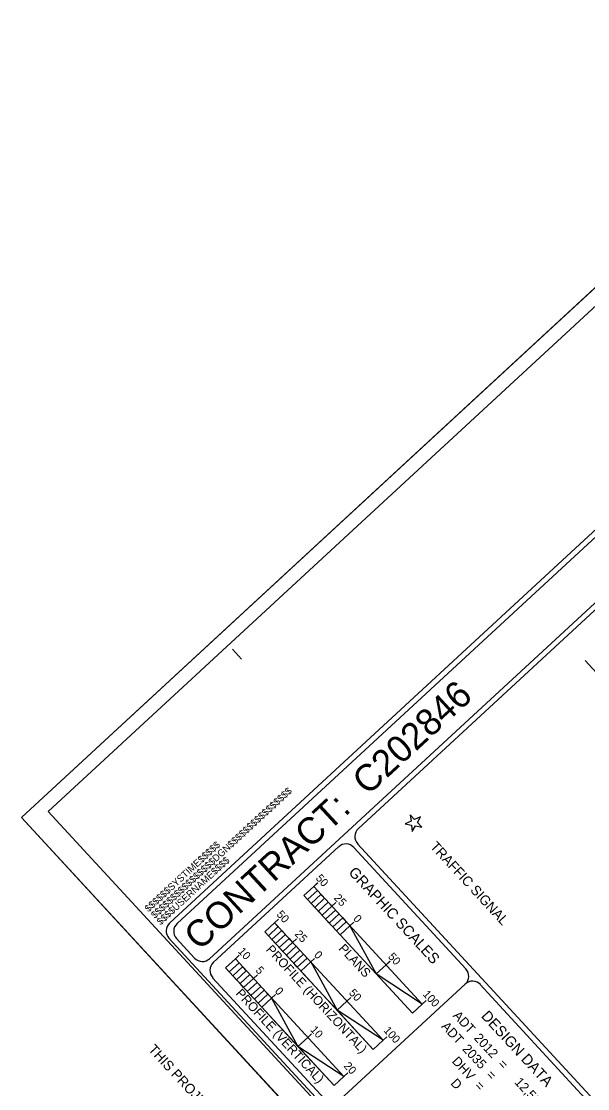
# Model space of a CAD drawing. Extents: x 1695041 to 1706254, y 786537 to 798223.
# Drawn here: x 1700402 to 1701995, y 795222 to 798223 of the extents above; entities that cross this region are included whole.
import ezdxf

# ---------------------------------------------------------------- set-up
doc = ezdxf.new("R2010")
doc.units = 0
for name, color, linetype in [('Old_Level_1', 7, 'Continuous'), ('Old_Level_23', 7, 'Continuous'), ('Prop RDY Traffic Signal CELL', 7, 'Continuous'), ('Sheet Cutting Line CELL', 7, 'Continuous'), ('Sheet Data Field CELL', 7, 'Continuous'), ('Sheet Plot Border Inside CELL', 7, 'Continuous'), ('Sheet Plot Border Outside CELL', 7, 'Continuous'), ('Sheet Title CELL', 7, 'Continuous')]:
    doc.layers.add(name, color=color, linetype=linetype)

msp = doc.modelspace()

# ---------------------------------------------------------------- linework, layer by layer
at = {"layer": 'Old_Level_1'}
msp.add_line((1702586.7, 795776.6), (1701987.7, 796425.6), dxfattribs=at)
at = {"layer": 'Prop RDY Traffic Signal CELL'}
msp.add_lwpolyline([(1701508.4, 795978.9), (1701496.1, 795992.3), (1701498.3, 795974.3), (1701481.8, 795966.7), (1701499.6, 795963.1), (1701501.7, 795945.1), (1701510.6, 795960.9), (1701528.4, 795957.4), (1701516.1, 795970.7), (1701524.9, 795986.5), (1701508.4, 795978.9)], dxfattribs=at)
at = {"layer": 'Sheet Cutting Line CELL'}
for p, q in [((1702826.9, 798222.8), (1700402.1, 795984.5)), ((1700402.1, 795984.5), (1703828.7, 792272.3))]:
    msp.add_line(p, q, dxfattribs=at)
at = {"layer": 'Sheet Data Field CELL'}
for p, q in [((1701224.7, 795790.5), (1701235.7, 795800.6)), ((1701275.5, 795735.3), (1701286.6, 795745.5)), ((1700797, 795667.2), (1700797, 795667.2)), ((1701428.2, 795570), (1701439.2, 795580.2)), ((1701529.9, 795459.8), (1701540.9, 795470))]:
    msp.add_line(p, q, dxfattribs=at)
at = {"layer": 'Sheet Plot Border Inside CELL'}
msp.add_lwpolyline([(1700478, 796001.5), (1703869.1, 792327.8), (1706194.9, 794474.8), (1702803.9, 798148.4)], close=True, dxfattribs=at)
at = {"layer": 'Sheet Plot Border Outside CELL'}
msp.add_lwpolyline([(1706253.6, 794510.5), (1702826.9, 798222.8), (1700402.1, 795984.5), (1703828.7, 792272.3)], close=True, dxfattribs=at)
at = {"layer": 'Sheet Title CELL'}
for p, q in [((1700931.8, 795587.5), (1703180.3, 797663.1)), ((1701349.8, 795953), (1703190.5, 797652)), ((1700996.3, 796457.5), (1701021.8, 796430)), ((1700996.3, 796457.5), (1701021.8, 796430)), ((1700942, 795576.5), (1701294.7, 795902.1)), ((1701337.1, 795900.4), (1701652.5, 795558.7)), ((1701348.1, 795910.6), (1704237.6, 792780.3)), ((1701224.6, 795790.5), (1701197.1, 795765)), ((1701224.6, 795790.5), (1701235.6, 795800.6)), ((1701224.6, 795790.5), (1701224.6, 795790.5)), ((1701529.9, 795459.8), (1701224.6, 795790.5)), ((1701235.6, 795800.6), (1701235.6, 795800.6)), ((1701197.1, 795765), (1701502.3, 795434.3)), ((1701275.5, 795735.3), (1701286.5, 795745.5)), ((1701114.4, 795688.7), (1701086.9, 795663.3)), ((1701114.4, 795688.7), (1701125.4, 795698.9)), ((1701114.4, 795688.7), (1701125.4, 795698.9)), ((1701114.4, 795688.7), (1701114.4, 795688.7)), ((1701419.6, 795358.1), (1701114.4, 795688.7)), ((1701114.4, 795688.7), (1701114.4, 795688.7)), ((1701419.6, 795358.1), (1701114.4, 795688.7)), ((1701125.4, 795698.9), (1701125.4, 795698.9)), ((1701295.9, 795713.3), (1701268.3, 795687.9)), ((1701326.4, 795680.2), (1701337.4, 795690.4)), ((1700797, 795667.2), (1700797, 795667.2)), ((1700797, 795667.2), (1700797, 795667.2)), ((1700797, 795667.2), (1700797, 795667.2)), ((1700797, 795667.2), (1700797, 795667.2)), ((1701086.9, 795663.3), (1701392.1, 795332.6)), ((1701165.3, 795633.6), (1701176.3, 795643.8)), ((1701165.3, 795633.6), (1701176.3, 795643.8)), ((1701004.2, 795586.9), (1701015.2, 795597.1)), ((1701004.2, 795586.9), (1701015.2, 795597.1)), ((1701004.2, 795586.9), (1701015.2, 795597.1)), ((1701015.2, 795597.1), (1701015.2, 795597.1)), ((1701185.6, 795611.5), (1701158.1, 795586.1)), ((1701004.2, 795586.9), (1700976.6, 795561.5)), ((1701004.2, 795586.9), (1701004.2, 795586.9)), ((1701309.4, 795256.3), (1701004.2, 795586.9)), ((1701004.2, 795586.9), (1701004.2, 795586.9)), ((1701309.4, 795256.3), (1701004.2, 795586.9)), ((1701004.2, 795586.9), (1701004.2, 795586.9)), ((1701309.4, 795256.3), (1701004.2, 795586.9)), ((1701216.2, 795578.5), (1701227.2, 795588.6)), ((1701216.2, 795578.5), (1701227.2, 795588.6)), ((1701428.1, 795570), (1701400.6, 795544.6)), ((1701428.1, 795570), (1701439.1, 795580.2)), ((1700976.6, 795561.5), (1701281.9, 795230.9)), ((1701055.1, 795531.9), (1701066.1, 795542)), ((1701055.1, 795531.9), (1701066.1, 795542)), ((1701055.1, 795531.9), (1701066.1, 795542)), ((1701075.4, 795509.8), (1701047.8, 795484.4)), ((1701650.8, 795516.3), (1701298.1, 795190.7)), ((1701693.2, 795514.6), (1701988.3, 795195)), ((1701105.9, 795476.8), (1701117, 795486.9)), ((1701105.9, 795476.8), (1701117, 795486.9)), ((1701105.9, 795476.8), (1701117, 795486.9)), ((1701317.9, 795468.3), (1701328.9, 795478.4)), ((1701317.9, 795468.3), (1701328.9, 795478.4)), ((1701317.9, 795468.3), (1701290.4, 795442.8)), ((1701502.3, 795434.3), (1701529.9, 795459.8)), ((1701529.9, 795459.8), (1701540.9, 795470)), ((1701207.7, 795366.5), (1701180.1, 795341.1)), ((1701207.7, 795366.5), (1701218.7, 795376.7)), ((1701207.7, 795366.5), (1701218.7, 795376.7)), ((1701207.7, 795366.5), (1701218.7, 795376.7)), ((1701392.1, 795332.6), (1701419.6, 795358.1)), ((1701419.6, 795358.1), (1701430.7, 795368.2)), ((1701419.6, 795358.1), (1701430.7, 795368.2)), ((1701309.4, 795256.3), (1701320.4, 795266.5)), ((1701309.4, 795256.3), (1701320.4, 795266.5)), ((1701309.4, 795256.3), (1701320.4, 795266.5)), ((1701281.9, 795230.9), (1701309.4, 795256.3))]:
    msp.add_line(p, q, dxfattribs=at)
for points in [[(1703089.6, 797783.5), (1700819.1, 795687.6)], [(1703089.6, 797783.5), (1700819.1, 795687.6)], [(1703088.8, 797762.2), (1700840.3, 795686.7)], [(1700817.3, 795645.2), (1703828.9, 792382.6)], [(1700838.5, 795644.4), (1700889.4, 795589.2)], [(1700940.3, 795534.1), (1701255.7, 795192.4)]]:
    msp.add_lwpolyline(points, dxfattribs=at)
for points in [[(1701224.6, 795790.5), (1701234.8, 795779.4), (1701207.3, 795754), (1701197.1, 795765)], [(1701245, 795768.4), (1701255.1, 795757.4), (1701227.6, 795731.9), (1701217.4, 795742.9)], [(1701265.3, 795746.3), (1701275.5, 795735.3), (1701248, 795709.9), (1701237.8, 795720.9)], [(1701285.7, 795724.3), (1701295.9, 795713.3), (1701268.3, 795687.9), (1701258.1, 795698.9)], [(1701114.4, 795688.7), (1701124.6, 795677.7), (1701097, 795652.3), (1701086.9, 795663.3)], [(1701306, 795702.3), (1701316.2, 795691.3), (1701288.6, 795665.8), (1701278.5, 795676.8)], [(1701134.8, 795666.7), (1701144.9, 795655.7), (1701117.4, 795630.2), (1701107.2, 795641.2)], [(1701326.4, 795680.2), (1701400.6, 795544.6), (1701298.8, 795654.8)], [(1701155.1, 795644.6), (1701165.3, 795633.6), (1701137.7, 795608.2), (1701127.5, 795619.2)], [(1701175.4, 795622.6), (1701185.6, 795611.5), (1701158.1, 795586.1), (1701147.9, 795597.1)], [(1701195.8, 795600.5), (1701206, 795589.5), (1701178.4, 795564.1), (1701168.3, 795575.1)], [(1701004.2, 795586.9), (1701014.4, 795575.9), (1700986.8, 795550.5), (1700976.6, 795561.5)], [(1701024.6, 795564.9), (1701034.7, 795553.9), (1701007.2, 795528.5), (1700997, 795539.5)], [(1701216.2, 795578.5), (1701290.4, 795442.8), (1701188.6, 795553)], [(1701044.9, 795542.9), (1701055.1, 795531.9), (1701027.5, 795506.4), (1701017.3, 795517.5)], [(1701529.9, 795459.8), (1701400.6, 795544.6), (1701502.3, 795434.3)], [(1701065.2, 795520.8), (1701075.4, 795509.8), (1701047.8, 795484.4), (1701037.7, 795495.4)], [(1701085.6, 795498.8), (1701095.8, 795487.8), (1701068.2, 795462.3), (1701058, 795473.4)], [(1701105.9, 795476.8), (1701180.1, 795341.1), (1701078.4, 795451.3)], [(1701419.6, 795358.1), (1701290.4, 795442.8), (1701392.1, 795332.6)], [(1701309.4, 795256.3), (1701180.1, 795341.1), (1701281.9, 795230.9)]]:
    msp.add_lwpolyline(points, close=True, dxfattribs=at)
for centre, start, end in [((1701370.3, 795931), 132.7091, 222.7091), ((1701315.2, 795880.1), 42.7091, 132.7091), ((1700839.5, 795665.6), 132.7091, 222.7091), ((1700860.7, 795664.8), 132.7091, 222.7091), ((1700911.6, 795609.7), 222.7091, 312.7091), ((1700962.5, 795554.6), 132.7091, 222.7091), ((1701630.6, 795538.4), 312.7091, 42.7091), ((1701671.3, 795494.4), 42.7091, 132.7091)]:
    msp.add_arc(centre, 30, start, end, dxfattribs=at)

# ---------------------------------------------------------------- texts
at = {"layer": 'Old_Level_23'}
for s, p in [('TRAFFIC SIGNAL', (1701550.2, 795901.4)), ('THIS PROJECT IS WITHIN THE MUNICIPAL BOUNDARY OF HIGH POINT', (1700757.4, 795330.9))]:
    msp.add_text(s, height=27.682, rotation=312.7091, dxfattribs=at).set_placement(p)
at = {"layer": 'Sheet Data Field CELL'}
for s, height, p in [('50', 22.5, (1701228.8, 795812.5)), ('25', 22.5, (1701279.9, 795757.1)), ('50', 22.5, (1701118.6, 795710.7)), ('25', 22.5, (1701169.7, 795655.4)), ('10', 22.5, (1701010.2, 795607)), ('50', 22.5, (1701432.3, 795592)), ('5 ', 22.5, (1701059.5, 795553.6)), ('50', 22.5, (1701322.1, 795490.3)), ('100', 22.5, (1701529.9, 795486.4)), ('ADT', 26.25, (1701614.7, 795426.3)), ('10', 22.5, (1701213.7, 795386.6)), ('100', 22.5, (1701419.6, 795384.7)), ('ADT', 26.25, (1701581.9, 795396)), ('2012', 26.25, (1701673.5, 795363.2)), ('2035', 26.25, (1701640.9, 795332.5)), ('20 ', 22.5, (1701307.6, 795284.9)), ('DHV', 26.25, (1701611.7, 795297.8)), ('=', 26.3, (1701740.9, 795289.8)), ('=', 26.3, (1701707.8, 795259.3)), ('D', 26.3, (1701607.9, 795236)), ('=', 26.3, (1701675.1, 795229.1)), ('12,500   ', 26.25, (1701787.6, 795239.1))]:
    msp.add_text(s, height=height, rotation=312.7091, dxfattribs=at).set_placement(p)
at = {"layer": 'Sheet Title CELL'}
for s, height, rotation, p in [('C202846   ', 75, 42.7091, (1701376.4, 796044.4)), ('$$$$$$$$$$$$$$$$DGN$$$$$$$$$$$$$$$$', 19.688, 42.7091, (1700777.7, 795699.3)), ('CONTRACT:', 75, 42.7091, (1700903.1, 795607.5)), ('$$$$$$SYSTIME$$$$$', 19.688, 42.7091, (1700759.9, 795717.5)), ('$$$$USERNAME$$$$', 19.688, 42.7091, (1700794, 795680.8)), ('GRAPHIC SCALES', 29.999, 312.7091, (1701320.7, 795828.8)), ('0', 22.5, 312.7091, (1701334.3, 795698.8)), ('PROFILE (HORIZONTAL)', 25.499, 312.7091, (1701088.8, 795611.8)), ('PLANS', 25.5, 312.7091, (1701293, 795614.7)), ('0', 22.5, 312.7091, (1701223.8, 795596.8)), ('0', 22.5, 312.7091, (1701224.1, 795597.1)), ('PROFILE (VERTICAL)', 25.499, 312.7091, (1701003.5, 795488.6)), ('0', 22.5, 312.7091, (1701113.6, 795495)), ('0', 22.5, 312.7091, (1701113.6, 795495)), ('0', 22.5, 312.7091, (1701113.9, 795495.3)), ('DESIGN DATA', 29.999, 312.7091, (1701693.8, 795424.8))]:
    msp.add_text(s, height=height, rotation=rotation, dxfattribs=at).set_placement(p)

doc.saveas('drawing.dxf')
